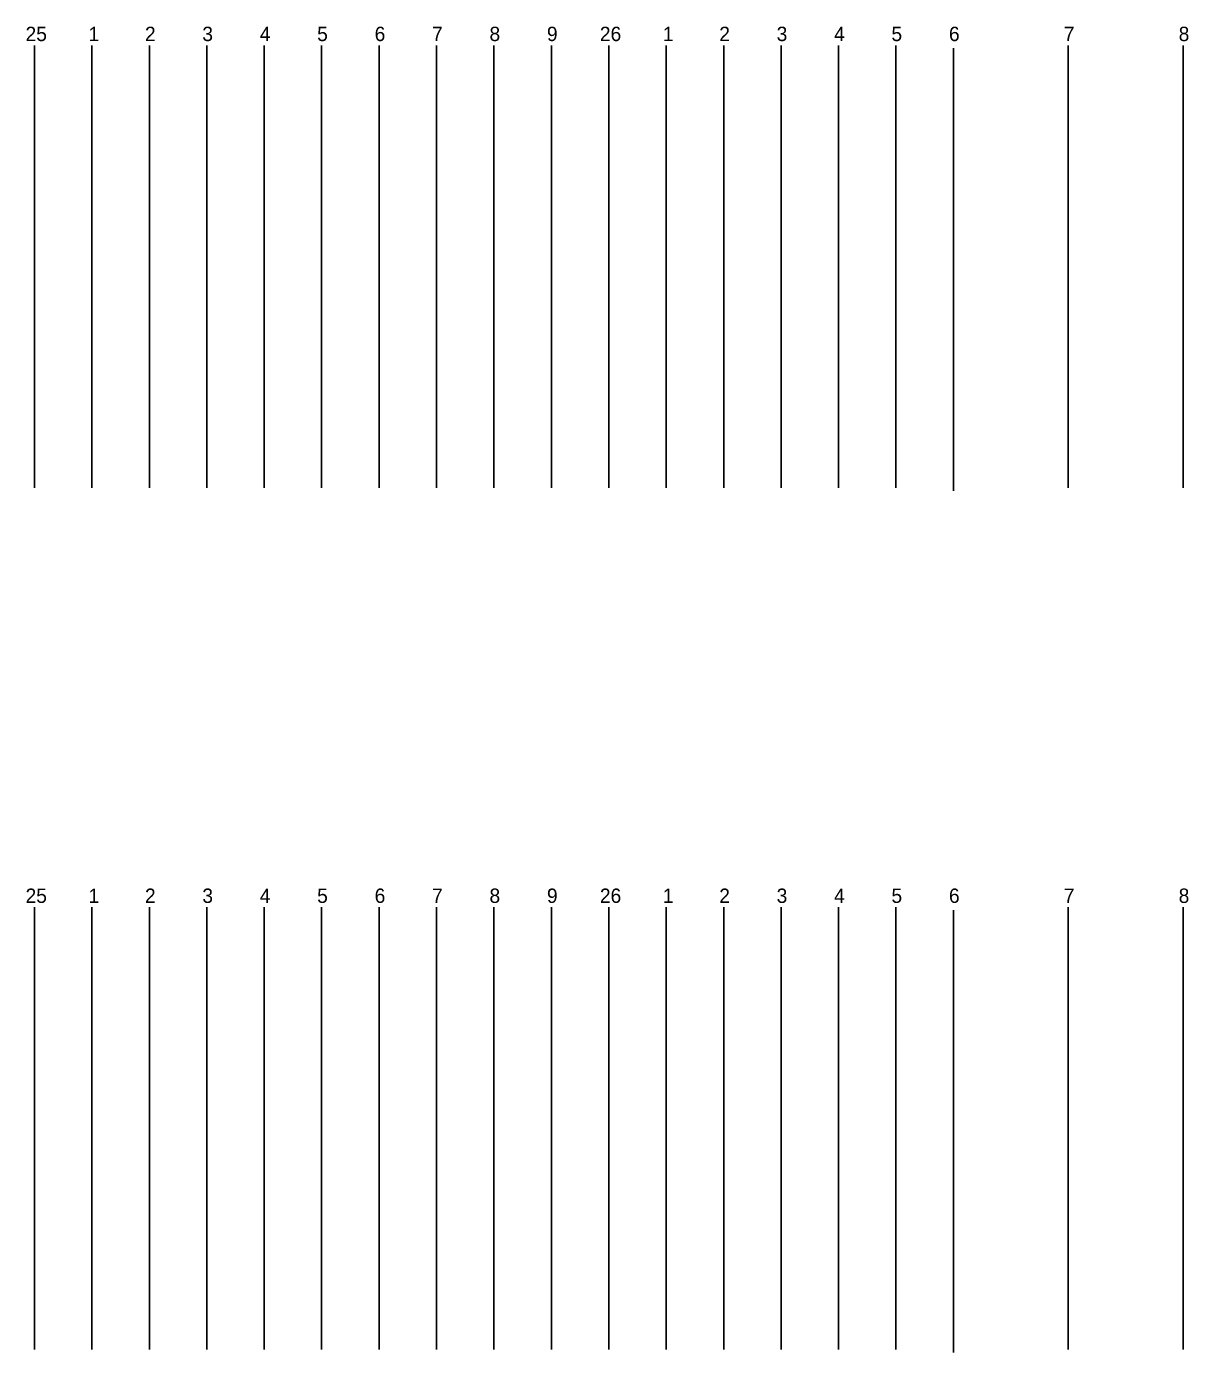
# Model space of a CAD drawing. Extents: x 2343 to 7744, y -5880 to 2050.
# Drawn here: x 5717.2 to 6121.9, y -5455 to -4993.4 of the extents above; entities that cross this region are included whole.
import ezdxf

# ---------------------------------------------------------------- set-up
doc = ezdxf.new("R2010")
doc.units = 0
doc.layers.add('Vrstva 1', color=7, linetype='Continuous')

msp = doc.modelspace()

# ---------------------------------------------------------------- linework, layer by layer
for p, q in [((5720, -5000), (5720, -5154)), ((5740, -5000), (5740, -5154)), ((5760, -5000), (5760, -5154)), ((5780, -5000), (5780, -5154)), ((5800, -5000), (5800, -5154)), ((5800, -5000), (5800, -5154)), ((5820, -5000), (5820, -5154)), ((5840, -5000), (5840, -5154)), ((5860, -5000), (5860, -5154)), ((5880, -5000), (5880, -5154)), ((5900, -5000), (5900, -5154)), ((5920, -5000), (5920, -5154)), ((5940, -5000), (5940, -5154)), ((5960, -5000), (5960, -5154)), ((5980, -5000), (5980, -5154)), ((6000, -5000), (6000, -5154)), ((6020, -5000), (6020, -5154)), ((6040, -5001), (6040, -5155)), ((6080, -5000), (6080, -5154)), ((6120, -5000), (6120, -5154)), ((5720, -5300), (5720, -5454)), ((5740, -5300), (5740, -5454)), ((5760, -5300), (5760, -5454)), ((5780, -5300), (5780, -5454)), ((5800, -5300), (5800, -5454)), ((5800, -5300), (5800, -5454)), ((5820, -5300), (5820, -5454)), ((5840, -5300), (5840, -5454)), ((5860, -5300), (5860, -5454)), ((5880, -5300), (5880, -5454)), ((5900, -5300), (5900, -5454)), ((5920, -5300), (5920, -5454)), ((5940, -5300), (5940, -5454)), ((5960, -5300), (5960, -5454)), ((5980, -5300), (5980, -5454)), ((6000, -5300), (6000, -5454)), ((6020, -5300), (6020, -5454)), ((6040, -5301), (6040, -5455)), ((6080, -5300), (6080, -5454)), ((6120, -5300), (6120, -5454))]:
    msp.add_line(p, q)

# ---------------------------------------------------------------- texts
at = {"layer": 'Vrstva 1'}
for s, p in [('25', (5716.88, -4998.5)), ('1', (5738.84, -4998.5)), ('2', (5758.47, -4998.5)), ('3', (5778.45, -4998.5)), ('4', (5798.46, -4998.5)), ('5', (5818.43, -4998.5)), ('6', (5838.45, -4998.5)), ('7', (5858.45, -4998.5)), ('8', (5878.45, -4998.5)), ('9', (5898.45, -4998.5)), ('26', (5916.89, -4998.5)), ('1', (5938.84, -4998.5)), ('2', (5958.47, -4998.5)), ('3', (5978.45, -4998.5)), ('4', (5998.46, -4998.5)), ('5', (6018.43, -4998.5)), ('6', (6038.45, -4998.5)), ('7', (6078.45, -4998.5)), ('8', (6118.45, -4998.5)), ('25', (5716.88, -5298.5)), ('1', (5738.84, -5298.5)), ('2', (5758.47, -5298.5)), ('3', (5778.45, -5298.5)), ('4', (5798.46, -5298.5)), ('5', (5818.43, -5298.5)), ('6', (5838.45, -5298.5)), ('7', (5858.45, -5298.5)), ('8', (5878.45, -5298.5)), ('9', (5898.45, -5298.5)), ('26', (5916.89, -5298.5)), ('1', (5938.84, -5298.5)), ('2', (5958.47, -5298.5)), ('3', (5978.45, -5298.5)), ('4', (5998.46, -5298.5)), ('5', (6018.43, -5298.5)), ('6', (6038.45, -5298.5)), ('7', (6078.45, -5298.5)), ('8', (6118.45, -5298.5))]:
    msp.add_text(s, height=5, dxfattribs=at).set_placement(p)

doc.saveas('drawing.dxf')
